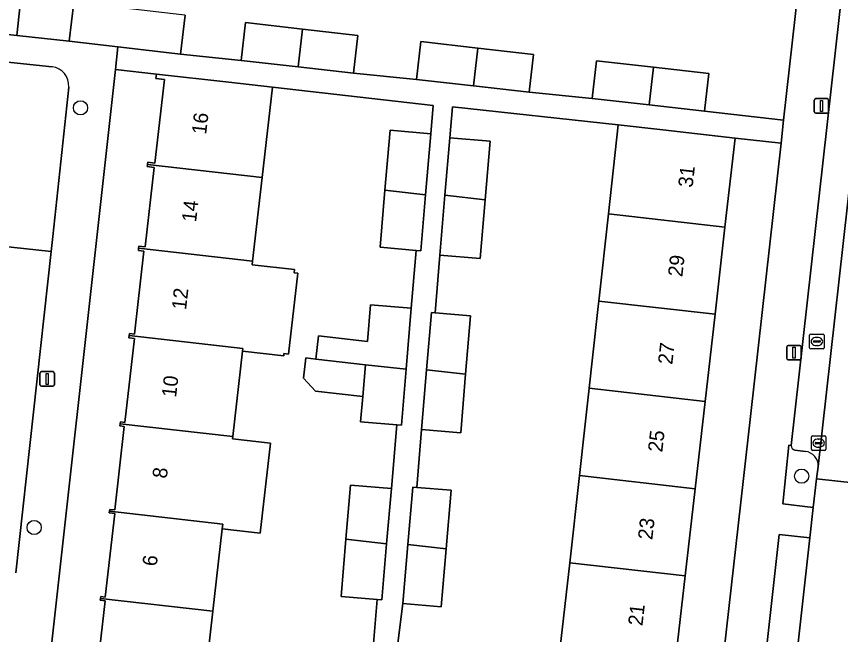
# Model space of a CAD drawing. Extents: x 161928 to 163071, y 386474 to 387428.
# Drawn here: x 162133 to 162189.6, y 386672 to 386714.4 of the extents above; entities that cross this region are included whole.
import ezdxf

# ---------------------------------------------------------------- set-up
doc = ezdxf.new("R2010")
doc.units = 0
for name, color, linetype in [('IMGEO_Boom', 7, 'Continuous'), ('IMGEO_Erf', 7, 'Continuous'), ('IMGEO_Groenvoorziening', 7, 'Continuous'), ('IMGEO_Kolk', 7, 'Continuous'), ('IMGEO_Lichtmast', 7, 'Continuous'), ('IMGEO_Pand', 7, 'Continuous'), ('IMGEO_Pand_nummerreeks', 7, 'Continuous'), ('IMGEO_Parkeervlak_open', 7, 'Continuous'), ('IMGEO_Rijbaan_lokaal_open', 7, 'Continuous'), ('IMGEO_Rioolput', 7, 'Continuous'), ('IMGEO_Voetpad_open', 7, 'Continuous')]:
    doc.layers.add(name, color=color, linetype=linetype)

msp = doc.modelspace()

# ---------------------------------------------------------------- linework, layer by layer
at = {"layer": 'IMGEO_Boom'}
for centre in [(162137.385, 386708.154), (162186.925, 386682.856), (162134.203, 386679.327)]:
    msp.add_circle(centre, 0.489, dxfattribs=at)
at = {"layer": 'IMGEO_Erf'}
for points in [[(162135.777, 386738.852), (162133.024, 386713.116), (162136.616, 386712.732), (162136.924, 386715.398)], [(162144.567, 386714.515), (162144.259, 386711.849), (162148.416, 386711.415), (162148.711, 386714.009), (162152.628, 386713.563), (162156.442, 386713.128), (162156.147, 386710.535), (162160.474, 386710.106), (162160.769, 386712.7), (162164.686, 386712.254), (162168.5, 386711.819), (162168.205, 386709.226), (162172.531, 386708.796), (162172.826, 386711.39), (162176.743, 386710.944), (162180.557, 386710.509), (162180.262, 386707.916), (162185.687, 386707.307), (162188.314, 386730.719)], [(162138.417, 386668.477), (162139.076, 386674.297), (162138.749, 386674.334), (162138.763, 386674.458), (162138.777, 386674.58), (162139.085, 386674.545), (162139.735, 386680.287), (162139.368, 386680.329), (162139.382, 386680.45), (162139.395, 386680.571), (162139.743, 386680.532), (162140.393, 386686.272), (162140.099, 386686.305), (162140.115, 386686.445), (162140.13, 386686.583), (162140.438, 386686.548), (162141.093, 386692.318), (162140.715, 386692.361), (162140.732, 386692.51), (162140.748, 386692.658), (162141.092, 386692.619), (162141.738, 386698.316), (162141.361, 386698.359), (162141.378, 386698.508), (162141.394, 386698.656), (162141.833, 386698.606), (162142.452, 386704.066), (162141.97, 386704.12), (162141.987, 386704.268), (162142.004, 386704.416), (162142.501, 386704.36), (162143.151, 386710.095), (162142.569, 386710.161), (162142.605, 386710.472), (162139.782, 386710.786), (162134.429, 386662.587)], [(162157.4, 386669.982), (162157.774, 386674.386), (162155.291, 386674.597), (162155.624, 386678.522), (162155.94, 386682.246), (162158.742, 386682.008), (162159.113, 386686.375), (162156.629, 386686.586), (162156.777, 386688.328), (162153.541, 386688.696), (162152.704, 386689.58), (162152.863, 386690.977), (162153.549, 386690.899), (162153.729, 386692.485), (162157.097, 386692.102), (162157.311, 386694.626), (162160.113, 386694.388), (162160.451, 386698.364), (162157.967, 386698.575), (162158.3, 386702.5), (162158.649, 386706.615), (162161.451, 386706.377), (162161.616, 386708.318), (162150.567, 386709.569), (162149.865, 386703.376), (162149.212, 386697.62), (162149.185, 386697.381), (162152.089, 386697.052), (162152.064, 386696.828), (162152.315, 386696.8), (162151.685, 386691.232), (162151.362, 386691.269), (162151.346, 386691.13), (162148.513, 386691.451), (162147.846, 386685.569), (162147.83, 386685.424), (162150.431, 386685.129), (162149.73, 386678.938), (162147.128, 386679.233), (162146.487, 386673.582), (162145.797, 386667.496)], [(162170.323, 386670.912), (162170.997, 386676.905), (162171.672, 386682.898), (162172.043, 386686.226), (162172.335, 386688.891), (162172.565, 386690.974), (162172.954, 386694.515), (162172.994, 386694.885), (162173.653, 386700.879), (162174.323, 386706.981), (162162.936, 386708.231), (162162.756, 386706.094), (162165.521, 386705.862), (162165.183, 386701.843), (162164.843, 386697.796), (162162.077, 386698.028), (162161.745, 386694.079), (162164.182, 386693.874), (162163.844, 386689.855), (162163.506, 386685.836), (162160.816, 386686.062), (162160.482, 386682.085), (162162.844, 386681.887), (162162.506, 386677.867), (162162.171, 386673.883), (162159.537, 386674.105), (162159.033, 386670.106)]]:
    msp.add_lwpolyline(points, dxfattribs=at)
msp.add_lwpolyline([(162185.509, 386705.724), (162182.357, 386706.078), (162181.659, 386699.965), (162180.974, 386693.974), (162180.29, 386687.983), (162179.605, 386681.992), (162178.92, 386676), (162178.236, 386670.009), (162177.551, 386664.018), (162176.853, 386657.905), (162180.101, 386657.532), (162183.403, 386686.958)], close=True, dxfattribs=at)
at = {"layer": 'IMGEO_Groenvoorziening'}
for points in [[(162186.2, 386684.968), (162186.051, 386684.981), (162185.624, 386680.944), (162187.711, 386680.712), (162187.957, 386682.681), (162188.068, 386683.529)], [(162187.186, 386684.554), (162186.467, 386684.645)]]:
    msp.add_lwpolyline(points, dxfattribs=at)
for centre, radius, start, end in [((162186.522, 386684.963), 0.322, 179.0314, 260.1246), ((162187.075, 386683.567), 0.994, 357.8299, 83.5933)]:
    msp.add_arc(centre, radius, start, end, dxfattribs=at)
at = {"layer": 'IMGEO_Kolk'}
for p, q in [((162187.594, 386684.7), (162187.594, 386685.552)), ((162187.669, 386685.626), (162188.521, 386685.626)), ((162188.082, 386685.406), (162188.107, 386685.406)), ((162188.595, 386685.552), (162188.595, 386684.7)), ((162188.521, 386684.626), (162187.669, 386684.626)), ((162187.853, 386685.12), (162187.853, 386685.132)), ((162188.291, 386685.083), (162187.893, 386685.083)), ((162187.896, 386685.169), (162188.294, 386685.169)), ((162188.105, 386684.846), (162188.08, 386684.846)), ((162188.337, 386685.132), (162188.337, 386685.12))]:
    msp.add_line(p, q, dxfattribs=at)
for points in [[(162187.594, 386684.7), (162187.594, 386685.552)], [(162187.669, 386685.626), (162188.521, 386685.626)], [(162188.595, 386685.552), (162188.595, 386684.7)], [(162188.521, 386684.626), (162187.669, 386684.626)]]:
    msp.add_lwpolyline(points, dxfattribs=at)
for centre, radius, start, end in [((162187.671, 386685.55), 0.0765, 91.552, 178.448), ((162187.671, 386685.55), 0.0765, 91.552, 178.448), ((162188.519, 386685.55), 0.0765, 1.552, 88.448), ((162188.519, 386685.55), 0.0765, 1.552, 88.448), ((162187.671, 386684.702), 0.0765, 181.552, 268.448), ((162187.671, 386684.702), 0.0765, 181.552, 268.448), ((162187.893, 386685.129), 0.0403, 85.8775, 175.7526), ((162187.89, 386685.119), 0.0366, 178.938, 274.7102), ((162188.294, 386685.126), 0.043, 264.8664, 352.4533), ((162188.298, 386685.131), 0.0386, 1.7309, 96.639), ((162188.519, 386684.702), 0.0765, 271.552, 358.448), ((162188.519, 386684.702), 0.0765, 271.552, 358.448)]:
    msp.add_arc(centre, radius, start, end, dxfattribs=at)
for centre, major_axis, ratio, start_param, end_param in [((162188.081, 386685.126), (-0.387, 0.002), 0.722429, 4.712389, 7.853982), ((162188.106, 386685.126), (-0.39, 0.002), 0.717154, 1.570796, 4.712389)]:
    msp.add_ellipse(centre, major_axis=major_axis, ratio=ratio, start_param=start_param, end_param=end_param, dxfattribs=at)
at = {"layer": 'IMGEO_Lichtmast'}
for p, q in [((162187.792, 386707.886), (162187.792, 386708.686)), ((162187.792, 386708.686), (162187.792, 386707.886)), ((162187.892, 386708.786), (162188.682, 386708.786)), ((162188.682, 386708.786), (162187.892, 386708.786)), ((162188.782, 386708.686), (162188.782, 386707.886)), ((162188.782, 386707.886), (162188.782, 386708.686)), ((162188.682, 386707.786), (162187.892, 386707.786)), ((162187.892, 386707.786), (162188.682, 386707.786)), ((162185.908, 386690.935), (162185.908, 386691.735)), ((162185.908, 386691.735), (162185.908, 386690.935)), ((162186.008, 386691.835), (162186.798, 386691.835)), ((162186.798, 386691.835), (162186.008, 386691.835)), ((162186.898, 386691.735), (162186.898, 386690.935)), ((162186.898, 386690.935), (162186.898, 386691.735)), ((162186.798, 386690.835), (162186.008, 386690.835)), ((162186.008, 386690.835), (162186.798, 386690.835)), ((162134.605, 386689.135), (162134.605, 386689.935)), ((162134.605, 386689.935), (162134.605, 386689.135)), ((162134.705, 386690.035), (162135.495, 386690.035)), ((162135.495, 386690.035), (162134.705, 386690.035)), ((162135.595, 386689.935), (162135.595, 386689.135)), ((162135.595, 386689.135), (162135.595, 386689.935)), ((162135.495, 386689.035), (162134.705, 386689.035)), ((162134.705, 386689.035), (162135.495, 386689.035))]:
    msp.add_line(p, q, dxfattribs=at)
for points in [[(162188.212, 386708.661), (162188.362, 386708.661), (162188.362, 386707.911), (162188.212, 386707.911), (162188.212, 386708.661)], [(162186.328, 386691.71), (162186.478, 386691.71), (162186.478, 386690.96), (162186.328, 386690.96), (162186.328, 386691.71)], [(162135.025, 386689.91), (162135.175, 386689.91), (162135.175, 386689.16), (162135.025, 386689.16), (162135.025, 386689.91)]]:
    msp.add_lwpolyline(points, dxfattribs=at)
for centre, start, end in [((162187.892, 386708.686), 90, 180), ((162187.892, 386708.686), 90, 180), ((162188.682, 386708.686), 0, 90), ((162188.682, 386708.686), 360, 90), ((162187.892, 386707.886), 180, 270), ((162187.892, 386707.886), 180, 270), ((162188.682, 386707.886), 270, 0), ((162188.682, 386707.886), 270, 0), ((162186.008, 386691.735), 90, 180), ((162186.008, 386691.735), 90, 180), ((162186.798, 386691.735), 0, 90), ((162186.798, 386691.735), 360, 90), ((162186.008, 386690.935), 180, 270), ((162186.008, 386690.935), 180, 270), ((162186.798, 386690.935), 270, 0), ((162186.798, 386690.935), 270, 0), ((162134.705, 386689.935), 90, 180), ((162134.705, 386689.935), 90, 180), ((162135.495, 386689.935), 0, 90), ((162135.495, 386689.935), 360, 90), ((162134.705, 386689.135), 180, 270), ((162134.705, 386689.135), 180, 270), ((162135.495, 386689.135), 270, 0), ((162135.495, 386689.135), 270, 0)]:
    msp.add_arc(centre, 0.1, start, end, dxfattribs=at)
at = {"layer": 'IMGEO_Pand'}
for points in [[(162144.567, 386714.515), (162144.345, 386714.541), (162140.986, 386714.929), (162136.924, 386715.398), (162136.616, 386712.732), (162139.955, 386712.346), (162144.259, 386711.849)], [(162148.711, 386714.009), (162148.416, 386711.415), (162152.335, 386710.969), (162152.628, 386713.563)], [(162156.147, 386710.535), (162156.442, 386713.128), (162152.628, 386713.563), (162152.335, 386710.969)], [(162160.769, 386712.7), (162160.474, 386710.106), (162164.393, 386709.66), (162164.686, 386712.254)], [(162168.205, 386709.226), (162168.5, 386711.819), (162164.686, 386712.254), (162164.393, 386709.66)], [(162176.743, 386710.944), (162172.826, 386711.39), (162172.531, 386708.796), (162176.45, 386708.35)], [(162176.45, 386708.35), (162180.262, 386707.916), (162180.557, 386710.509), (162176.743, 386710.944)], [(162149.865, 386703.376), (162150.567, 386709.569), (162147.574, 386709.908), (162142.605, 386710.472), (162142.569, 386710.161), (162143.151, 386710.095), (162142.501, 386704.36), (162142.004, 386704.416), (162141.987, 386704.268)], [(162181.659, 386699.965), (162182.357, 386706.078), (162177.389, 386706.636), (162174.323, 386706.981), (162173.653, 386700.879)], [(162161.451, 386706.377), (162158.649, 386706.615), (162158.3, 386702.5), (162161.095, 386702.182)], [(162165.183, 386701.843), (162165.521, 386705.862), (162162.756, 386706.094), (162162.424, 386702.158)], [(162141.987, 386704.268), (162141.97, 386704.12), (162142.452, 386704.066), (162141.833, 386698.606), (162141.394, 386698.656), (162141.378, 386698.508), (162149.212, 386697.62), (162149.865, 386703.376)], [(162161.095, 386702.182), (162158.3, 386702.5), (162157.967, 386698.575), (162160.451, 386698.364), (162160.769, 386698.337)], [(162162.424, 386702.158), (162162.077, 386698.028), (162164.843, 386697.796), (162165.183, 386701.843)], [(162180.974, 386693.974), (162181.659, 386699.965), (162173.653, 386700.879), (162172.994, 386694.885)], [(162149.185, 386697.381), (162149.212, 386697.62), (162141.378, 386698.508), (162141.361, 386698.359), (162141.738, 386698.316), (162141.092, 386692.619), (162140.748, 386692.658), (162140.732, 386692.51), (162148.533, 386691.626), (162148.513, 386691.451), (162151.346, 386691.13), (162151.362, 386691.269), (162151.685, 386691.232), (162152.315, 386696.8), (162152.064, 386696.828), (162152.089, 386697.052)], [(162180.974, 386693.974), (162172.994, 386694.885), (162172.954, 386694.515), (162172.565, 386690.974), (162172.335, 386688.891), (162180.29, 386687.983)], [(162160.113, 386694.388), (162157.311, 386694.626), (162157.097, 386692.102), (162153.729, 386692.485), (162153.549, 386690.899), (162156.962, 386690.511), (162159.757, 386690.193)], [(162164.182, 386693.874), (162161.745, 386694.079), (162161.492, 386694.1), (162161.16, 386690.161), (162163.844, 386689.855)], [(162148.513, 386691.451), (162148.533, 386691.626), (162140.732, 386692.51), (162140.715, 386692.361), (162141.093, 386692.318), (162140.438, 386686.548), (162140.13, 386686.583), (162140.115, 386686.445), (162147.846, 386685.569)], [(162156.962, 386690.511), (162153.549, 386690.899), (162152.863, 386690.977), (162152.704, 386689.58), (162153.541, 386688.696), (162156.777, 386688.328)], [(162159.757, 386690.193), (162156.962, 386690.511), (162156.777, 386688.328), (162156.629, 386686.586), (162159.113, 386686.375), (162159.431, 386686.348)], [(162161.16, 386690.161), (162160.816, 386686.062), (162163.506, 386685.836), (162163.844, 386689.855)], [(162180.29, 386687.983), (162172.335, 386688.891), (162172.043, 386686.226), (162171.672, 386682.898), (162179.605, 386681.992)], [(162147.83, 386685.424), (162147.846, 386685.569), (162140.115, 386686.445), (162140.099, 386686.305), (162140.393, 386686.272), (162139.743, 386680.532), (162139.395, 386680.571), (162139.382, 386680.45), (162147.166, 386679.568), (162147.128, 386679.233), (162149.73, 386678.938), (162150.431, 386685.129)], [(162171.672, 386682.898), (162170.997, 386676.905), (162178.92, 386676), (162179.605, 386681.992)], [(162158.742, 386682.008), (162155.94, 386682.246), (162155.624, 386678.522), (162158.419, 386678.204)], [(162162.844, 386681.887), (162160.482, 386682.085), (162160.21, 386682.108), (162159.878, 386678.168), (162162.506, 386677.867)], [(162147.128, 386679.233), (162147.166, 386679.568), (162139.382, 386680.45), (162139.368, 386680.329), (162139.735, 386680.287), (162139.085, 386674.545), (162138.777, 386674.58), (162138.763, 386674.458), (162146.487, 386673.582)], [(162158.419, 386678.204), (162155.624, 386678.522), (162155.291, 386674.597), (162157.774, 386674.386), (162158.093, 386674.359)], [(162159.878, 386678.168), (162159.537, 386674.105), (162162.171, 386673.883), (162162.506, 386677.867)], [(162178.236, 386670.009), (162178.92, 386676), (162170.997, 386676.905), (162170.323, 386670.912)], [(162138.763, 386674.458), (162138.749, 386674.334), (162139.076, 386674.297), (162138.417, 386668.477), (162138.033, 386668.52), (162138.017, 386668.378), (162145.797, 386667.496), (162146.487, 386673.582)]]:
    msp.add_lwpolyline(points, close=True, dxfattribs=at)
at = {"layer": 'IMGEO_Parkeervlak_open'}
for points in [[(162188.068, 386683.529), (162193.241, 386729.689), (162193.15, 386729.453), (162193.004, 386729.146), (162192.831, 386728.854), (162192.632, 386728.578), (162192.41, 386728.321), (162192.166, 386728.084), (162191.901, 386727.871), (162191.678, 386727.7), (162191.471, 386727.511), (162191.282, 386727.303), (162191.112, 386727.079), (162190.963, 386726.841), (162190.872, 386726.64), (162186.2, 386684.968)], [(162135.45, 386710.968), (162131.706, 386711.363), (162130.362, 386711.505), (162128.996, 386698.98), (162135.365, 386698.285), (162135.477, 386699.307), (162136.578, 386709.583)], [(162132.956, 386676.203), (162135.365, 386698.285), (162128.996, 386698.98), (162126.123, 386672.637)], [(162186.467, 386684.645), (162187.186, 386684.554)]]:
    msp.add_lwpolyline(points, dxfattribs=at)
msp.add_lwpolyline([(162187.484, 386678.615), (162185.389, 386678.856), (162183.386, 386660.927), (162185.49, 386660.666)], close=True, dxfattribs=at)
for centre, radius, start, end in [((162135.298, 386709.693), 1.284, 355.0988, 83.2227), ((162186.522, 386684.963), 0.322, 179.0314, 260.1246), ((162187.075, 386683.567), 0.994, 357.8299, 83.5933)]:
    msp.add_arc(centre, radius, start, end, dxfattribs=at)
at = {"layer": 'IMGEO_Rijbaan_lokaal_open'}
for points in [[(162193.483, 386732.102), (162193.241, 386729.689), (162188.068, 386683.529), (162187.957, 386682.681), (162191.927, 386682.236), (162195.119, 386710.825)], [(162191.383, 386677.164), (162191.485, 386678.234), (162191.691, 386680.339), (162191.927, 386682.236), (162187.957, 386682.681), (162187.711, 386680.712), (162187.484, 386678.615), (162185.49, 386660.666), (162185.35, 386659.121), (162189.32, 386658.663), (162189.709, 386662.217), (162191.379, 386675.956)]]:
    msp.add_lwpolyline(points, dxfattribs=at)
at = {"layer": 'IMGEO_Rioolput'}
for p, q in [((162187.547, 386692.604), (162188.399, 386692.604)), ((162187.472, 386691.678), (162187.472, 386692.53)), ((162187.731, 386692.098), (162187.731, 386692.11)), ((162188.169, 386692.061), (162187.771, 386692.061)), ((162187.774, 386692.147), (162188.172, 386692.147)), ((162187.96, 386692.384), (162187.985, 386692.384)), ((162188.215, 386692.11), (162188.215, 386692.098)), ((162188.473, 386692.53), (162188.473, 386691.678)), ((162188.399, 386691.604), (162187.547, 386691.604)), ((162187.983, 386691.824), (162187.958, 386691.824))]:
    msp.add_line(p, q, dxfattribs=at)
for points in [[(162187.547, 386692.604), (162188.399, 386692.604)], [(162187.472, 386691.678), (162187.472, 386692.53)], [(162188.473, 386692.53), (162188.473, 386691.678)], [(162188.399, 386691.604), (162187.547, 386691.604)]]:
    msp.add_lwpolyline(points, dxfattribs=at)
for centre, radius, start, end in [((162187.549, 386692.528), 0.0765, 91.552, 178.448), ((162187.549, 386692.528), 0.0765, 91.552, 178.448), ((162188.397, 386692.528), 0.0765, 1.552, 88.448), ((162188.397, 386692.528), 0.0765, 1.552, 88.448), ((162187.771, 386692.107), 0.0403, 85.8775, 175.7526), ((162187.768, 386692.097), 0.0366, 178.938, 274.7102), ((162188.172, 386692.104), 0.043, 264.8664, 352.4533), ((162188.176, 386692.109), 0.0386, 1.7309, 96.639), ((162187.549, 386691.68), 0.0765, 181.552, 268.448), ((162187.549, 386691.68), 0.0765, 181.552, 268.448), ((162188.397, 386691.68), 0.0765, 271.552, 358.448), ((162188.397, 386691.68), 0.0765, 271.552, 358.448)]:
    msp.add_arc(centre, radius, start, end, dxfattribs=at)
for centre, major_axis, ratio, start_param, end_param in [((162187.959, 386692.104), (-0.387, 0.002), 0.722429, 4.712389, 7.853982), ((162187.984, 386692.104), (-0.39, 0.002), 0.717154, 1.570796, 4.712389)]:
    msp.add_ellipse(centre, major_axis=major_axis, ratio=ratio, start_param=start_param, end_param=end_param, dxfattribs=at)
at = {"layer": 'IMGEO_Voetpad_open'}
msp.add_lwpolyline([(162135.777, 386738.852), (162134.239, 386739.027), (162131.951, 386718.964), (162131.325, 386713.298), (162133.024, 386713.116)], close=True, dxfattribs=at)
for points in [[(162189.312, 386737.892), (162188.314, 386730.719), (162185.687, 386707.307), (162185.509, 386705.724), (162183.403, 386686.958), (162180.101, 386657.532), (162179.913, 386655.797), (162179.088, 386648.151)], [(162187.711, 386680.712), (162185.624, 386680.944), (162186.051, 386684.981), (162186.2, 386684.968), (162190.872, 386726.64), (162190.963, 386726.841), (162191.112, 386727.079), (162191.282, 386727.303), (162191.471, 386727.511), (162191.678, 386727.7), (162191.901, 386727.871), (162192.166, 386728.084), (162192.41, 386728.321), (162192.632, 386728.578), (162192.831, 386728.854), (162193.004, 386729.146), (162193.15, 386729.453), (162193.241, 386729.689), (162193.483, 386732.102)], [(162134.231, 386660.808), (162134.429, 386662.587), (162139.782, 386710.786), (162139.955, 386712.346), (162136.616, 386712.732), (162133.024, 386713.116), (162131.325, 386713.298), (162130.567, 386713.382), (162130.423, 386712.063), (162131.756, 386711.955), (162131.706, 386711.363), (162135.45, 386710.968)], [(162159.033, 386670.106), (162159.537, 386674.105), (162159.878, 386678.168), (162160.21, 386682.108), (162160.482, 386682.085), (162160.816, 386686.062), (162161.16, 386690.161), (162161.492, 386694.1), (162161.745, 386694.079), (162162.077, 386698.028), (162162.424, 386702.158), (162162.756, 386706.094), (162162.936, 386708.231), (162174.323, 386706.981), (162177.389, 386706.636), (162182.357, 386706.078), (162185.509, 386705.724), (162185.687, 386707.307), (162180.262, 386707.916), (162176.45, 386708.35), (162172.531, 386708.796), (162168.205, 386709.226), (162164.393, 386709.66), (162160.474, 386710.106), (162156.147, 386710.535), (162152.335, 386710.969), (162148.416, 386711.415), (162144.259, 386711.849), (162139.955, 386712.346), (162139.782, 386710.786), (162142.605, 386710.472), (162147.574, 386709.908), (162150.567, 386709.569), (162161.616, 386708.318), (162161.451, 386706.377), (162161.095, 386702.182), (162160.769, 386698.337), (162160.451, 386698.364), (162160.113, 386694.388), (162159.757, 386690.193), (162159.431, 386686.348), (162159.113, 386686.375), (162158.742, 386682.008), (162158.419, 386678.204), (162158.093, 386674.359), (162157.774, 386674.386), (162157.4, 386669.982)], [(162136.578, 386709.583), (162135.477, 386699.307), (162135.365, 386698.285), (162132.956, 386676.203)], [(162182.447, 386651.008), (162183.012, 386655.989), (162182.871, 386656.015), (162183.386, 386660.927), (162185.389, 386678.856), (162187.484, 386678.615), (162187.711, 386680.712)]]:
    msp.add_lwpolyline(points, dxfattribs=at)
msp.add_arc((162135.298, 386709.693), 1.284, 355.0988, 83.2227, dxfattribs=at)

# ---------------------------------------------------------------- texts
at = {"layer": 'IMGEO_Pand_nummerreeks'}
for s, rotation, p in [('16', 83.4704, (162146.017, 386706.29)), ('31', 83.4819, (162179.429, 386702.644)), ('14', 83.4704, (162145.328, 386700.268)), ('29', 83.4819, (162178.728, 386696.511)), ('12', 83.4685, (162144.638, 386694.243)), ('27', 83.48, (162178.039, 386690.489)), ('10', 83.4685, (162143.95, 386688.226)), ('25', 83.48, (162177.351, 386684.468)), ('8', 83.4685, (162143.313, 386682.662)), ('23', 83.4819, (162176.664, 386678.446)), ('6', 83.4685, (162142.622, 386676.636)), ('21', 83.4819, (162175.989, 386672.536))]:
    msp.add_text(s, height=1, rotation=rotation, dxfattribs=at).set_placement(p)

doc.saveas('drawing.dxf')
